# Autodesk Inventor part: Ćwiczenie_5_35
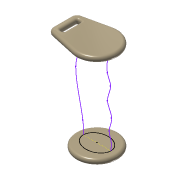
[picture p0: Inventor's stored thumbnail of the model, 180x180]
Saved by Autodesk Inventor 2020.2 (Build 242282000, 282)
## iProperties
Created: 2006-08
Part Number: Ćwiczenie_5_35
Document SubType Name: Modeling
Designer: F.Stasiak
Density: 1 g/cm^3
Material: Ogólny
Appearance: W kolorze pszenicy
Manager: www.cadconsulting.pl
Company: Fabian Stasiak CAD Consulting
Author: F.Stasiak
Subject: Zbiór ćwiczeń. Autodesk Inventor 2020. Kurs podstawowy
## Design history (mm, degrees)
sketch "Szkic1" dims "d0" = 20, "d1" = 16
  geometry: 2 further points; 1 other entity
  constraints: 1 coincident, 2 other
sketch "Szkic2"
  geometry: L1 (20, 0)-(-20, 0) reference; L2 (20, -12.733)-(20, 12.733); L3 (22.901, 100.257)-(22.901, 139.743); L4 (-20, -12.733)-(-20, 12.733); L5 (-17.099, 100.257)-(-17.099, 139.743); L6 (-17.099, 120)-(22.901, 120); A1 r 66.431 centre (-46.431, 0) between (19.233, -10.069) and (19.233, 10.069); A2 r 72.813 centre (95.714, 120) between (24.556, 135.435) and (24.556, 104.565); A3 r 19.539 centre (-39.539, 0) between (-22.213, -9.033) and (-22.213, 9.033); 11 further points
  constraints: 10 end point, 8 midpoint, 7 vertical, 3 centre point, 3 parallel, 3 point on circle, 1 coincident, 1 perpendicular, 20 other
  dimensions: "d2" = 120 distance from line of L6.end L1; "d3" = 40 distance of L6.start L6.end
sketch "Szkic3"
  geometry: C1 r 30 at (0, 0); 1 further point
  constraints: 1 centre point, 1 coincident
  dimensions: "d4" = 60 diameter of C1
extrude "Wyciągnięcie proste1" new body sketch "Szkic3" distance "d5" = 8; taper "d6" = 0 deg
fillet "Zaokrąglenie1"
node "Płaszczyzna konstrukcyjna1"
sketch "Szkic4"
  geometry: L1 (0, 0)-(40, 0) reference; L2 (23.592, 29.289)-(67.099, 19.644); L3 (67.099, 19.644)-(67.099, -19.644); L4 (67.099, -19.644)-(23.592, -29.289); A1 r 30 centre (17.099, 0) between (23.592, 29.289) and (23.592, -29.289); 1 further point
  constraints: 6 end point, 2 point on circle, 1 centre point, 1 coincident, 1 perpendicular, 1 tangent, 1 other
  dimensions: "d8" = 60 diameter of A1; "d9" = 50 distance from line of L3 point (17.099, 0); "d10" = 25 deg angle of L4 L2
extrude "Wyciągnięcie proste2" join sketch "Szkic4" distance "d11" = 8; taper "d12" = 0 deg
fillet "Zaokrąglenie2" dims "d13" = 8
fillet "Zaokrąglenie3"
sketch "Szkic5"
  geometry: L1 (-58.099, 13)-(-52.099, 13); L2 (-52.099, 13)-(-52.099, -13); L3 (-52.099, -13)-(-58.099, -13); L4 (-58.099, -13)-(-58.099, 13); L5 (-58.099, 0)-(-17.099, 0)
  constraints: 10 end point, 2 parallel, 2 perpendicular, 1 horizontal, 1 midpoint
  dimensions: "d14" = 26 distance of L3.end L1.start; "d15" = 6 distance of L2.end L3.end; "d16" = 35 distance from line of L5.end L2
extrude "Wyciągnięcie proste3" cut sketch "Szkic5" distance "d17" = 8; taper "d18" = 0 deg
fillet "Zaokrąglenie5" dims "d20" = 2
fillet "Zaokrąglenie6" dims "d21" = 3
node "Bryła1"
node "Korpusy bryłowe"
node "Korpusy powierzchniowe"
other parameters: "d7" = 0
